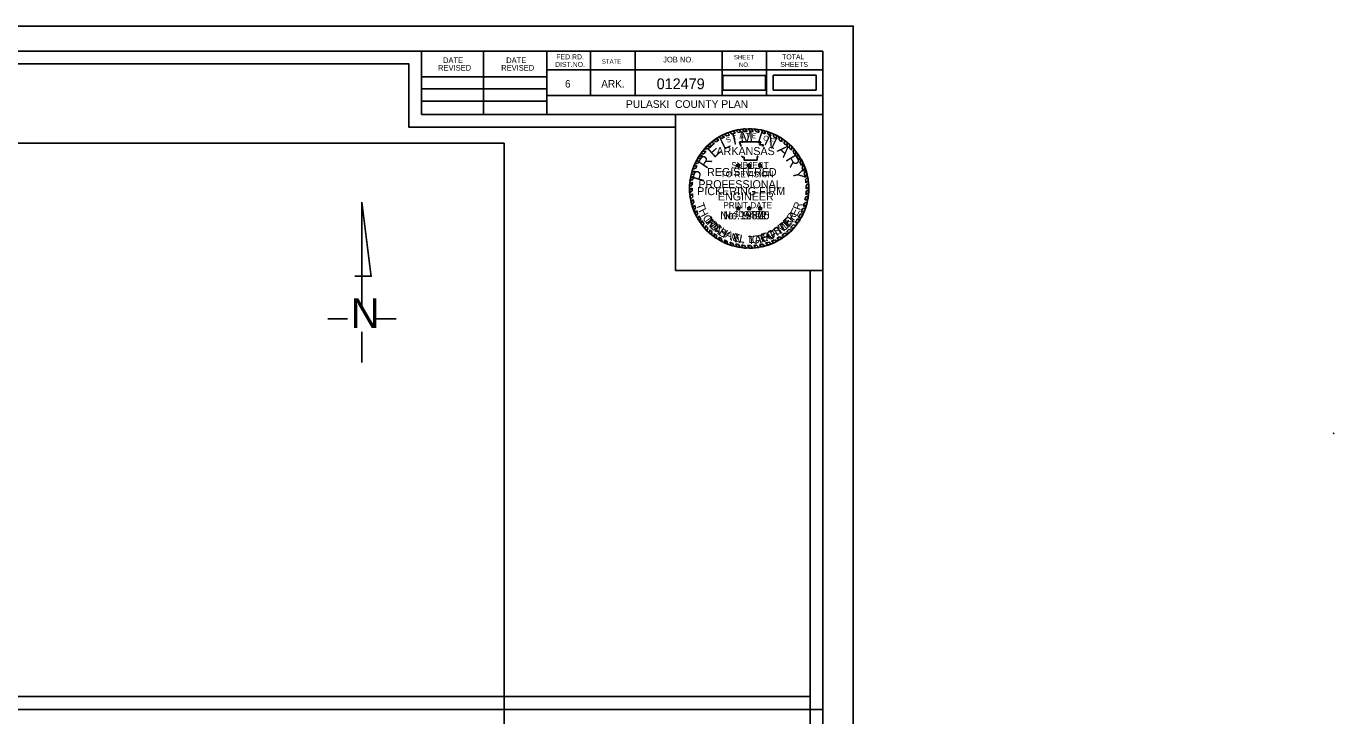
# Model space of a CAD drawing. Extents: x 10700 to 22009, y 10612 to 15552.
# Drawn here: x 19967 to 22009, y 14476 to 15552 of the extents above; entities that cross this region are included whole.
import ezdxf

# ---------------------------------------------------------------- set-up
doc = ezdxf.new("R2010")
doc.units = 0
for name, color, linetype in [('Default', 7, 'Continuous'), ('R_Border', 7, 'Continuous'), ('R_Border Notes', 7, 'Continuous'), ('R_Border Plan-Plan', 7, 'Continuous'), ('R_Draft', 7, 'Continuous'), ('R_No Plot', 7, 'Continuous'), ('STAMP_PE_CRAFTON', 7, 'Continuous'), ('STAMP_PE_FOSTER', 7, 'Continuous'), ('STAMP_PE_SEAL-INFO', 7, 'Continuous'), ('STAMP_PE_TAEGTMEYER', 7, 'Continuous'), ('STAMP_PE_TXT', 7, 'Continuous'), ('STAMP_PRELIMINARY', 7, 'Continuous')]:
    doc.layers.add(name, color=color, linetype=linetype)

msp = doc.modelspace()

# ---------------------------------------------------------------- linework, layer by layer
at = {"layer": 'Default'}
for points in [[(21054.8, 15452.2), (21121.6, 15452.2), (21121.6, 15475.3), (21054.8, 15475.3)], [(21133.5, 15452.3), (21200.3, 15452.3), (21200.3, 15475.4), (21133.5, 15475.4)], [(22008.3, 14916.3), (22008.8, 14916.3), (22008.8, 14916.8), (22008.3, 14916.8)]]:
    msp.add_lwpolyline(points, close=True, dxfattribs=at)
at = {"layer": 'R_Border'}
for p, q in [((18049.1, 15513.1), (21210.9, 15513.1)), ((20584.5, 15414.3), (20584.5, 15513.1)), ((20681.3, 15414.3), (20681.3, 15513.1)), ((20779.9, 15513.1), (20779.9, 15414.3)), ((20848.3, 15513.1), (20848.3, 15443.7)), ((20917.7, 15513.1), (20917.7, 15443.7)), ((21053.5, 15513.1), (21053.5, 15443.7)), ((21122.9, 15513.1), (21122.9, 15443.7)), ((21210.9, 13458.5), (21210.9, 15513.1)), ((21210.9, 15483.7), (20779.9, 15483.7)), ((21210.9, 15483.9), (21210.9, 15483.9)), ((20584.5, 15472.9), (20779.9, 15472.9)), ((20584.5, 15454.3), (20779.9, 15454.3)), ((21210.9, 15443.7), (20779.9, 15443.7)), ((20809.5, 15443.7), (21210.9, 15443.7)), ((20584.5, 15434.9), (20779.9, 15434.9)), ((21210.9, 15414.3), (20584.5, 15414.3))]:
    msp.add_line(p, q, dxfattribs=at)
at = {"layer": 'R_Border Plan-Plan'}
msp.add_line((18049.1, 14485.8), (21210.9, 14485.8), dxfattribs=at)
at = {"layer": 'R_Draft'}
for p, q in [((20491.3, 15277.2), (20505.9, 15160.8)), ((20491.3, 15114.5), (20491.3, 15277.2)), ((20480, 15161.7), (20505.9, 15161.7)), ((20437.8, 15095.3), (20468.7, 15095.3)), ((20511.9, 15095.3), (20544.8, 15095.3)), ((20491.3, 15027.2), (20491.3, 15075))]:
    msp.add_line(p, q, dxfattribs=at)
at = {"layer": 'R_No Plot'}
msp.add_line((17925.1, 15552.1), (21258.5, 15552.1), dxfattribs=at)
for points in [[(17925.1, 15552.1), (21258.5, 15552.1), (21258.5, 13418.7), (17925.1, 13418.7)], [(18069.1, 15493.1), (20564.5, 15493.1), (20564.5, 15394.3), (20739.9, 15394.3), (20980.9, 15394.3), (20980.9, 15171), (21190.9, 15171), (21190.9, 13478.5), (18069.1, 13478.5)], [(21190.9, 14505.8), (18069.1, 14505.8), (18069.1, 15493.1), (20564.5, 15493.1), (20564.5, 15394.3), (20739.9, 15394.3), (20980.9, 15394.3), (20980.9, 15171), (21190.9, 15171)], [(20980.9, 15414.3), (21210.9, 15414.3), (21210.9, 15171), (20980.9, 15171)], [(20713.4, 15369.5), (20713.4, 13848), (18546.7, 13848), (18546.7, 15369.5)]]:
    msp.add_lwpolyline(points, close=True, dxfattribs=at)
at = {"layer": 'STAMP_PE_SEAL-INFO'}
for p, q in [((21044.3, 15376.4), (21048.7, 15374.4)), ((21048.2, 15378.8), (21052.5, 15376.6)), ((21052.7, 15381.3), (21057.3, 15379.1)), ((21057, 15383.5), (21060.9, 15380.7)), ((21062, 15385.6), (21065, 15382.4)), ((21065.5, 15386.9), (21069.3, 15383.8)), ((21071.4, 15388.7), (21074.3, 15385.2)), ((21075.3, 15389.7), (21078.9, 15386.2)), ((21080.1, 15390.6), (21083.1, 15387)), ((21085.3, 15391.4), (21088.1, 15387.5)), ((21092.6, 15387.8), (21089.5, 15391.8)), ((21097.6, 15387.9), (21094.8, 15392)), ((21102.2, 15387.7), (21099.6, 15391.9)), ((21107.3, 15387.2), (21104.3, 15391.6)), ((21111.5, 15386.5), (21108.9, 15391.1)), ((21117.1, 15385.3), (21115.4, 15389.9)), ((21121.2, 15384.2), (21119.6, 15388.9)), ((21125.7, 15382.8), (21124.3, 15387.6)), ((21129.9, 15381.2), (21128.4, 15386.1)), ((21134.5, 15379.1), (21133.4, 15384.1)), ((21138.9, 15376.8), (21138.1, 15381.9)), ((21142.8, 15374.6), (21142.4, 15379.6)), ((21147.1, 15371.7), (21146.8, 15376.9)), ((21022.9, 15356.7), (21028.3, 15356.9)), ((21026.3, 15360.8), (21031.5, 15360.4)), ((21029.5, 15364.2), (21035, 15363.8)), ((21032.9, 15367.5), (21037.5, 15366.1)), ((21036.3, 15370.5), (21041.6, 15369.4)), ((21040.1, 15373.7), (21044.7, 15371.7)), ((21080.7, 15371.7), (21114.1, 15371.7)), ((21081.9, 15368.6), (21080.7, 15371.7)), ((21082.9, 15365.6), (21081.9, 15368.6)), ((21083, 15364.5), (21082.9, 15365.6)), ((21114.1, 15371.7), (21111.8, 15366.8)), ((21111.8, 15366.8), (21118.2, 15366.8)), ((21118.2, 15366.8), (21116.7, 15364.5)), ((21150.8, 15369), (21151.1, 15373.9)), ((21155.2, 15365.3), (21155.4, 15370.5)), ((21158.3, 15362.4), (21159, 15367.4)), ((21161.9, 15358.7), (21162.6, 15363.9)), ((21164.7, 15355.5), (21166, 15360.2)), ((21167.9, 15351.3), (21169.3, 15356.3)), ((21011.1, 15337.4), (21016.1, 15338.4)), ((21013, 15341.3), (21017.9, 15341.9)), ((21015.3, 15345.5), (21020.2, 15345.7)), ((21017.7, 15349.5), (21022.9, 15349.9)), ((21020.1, 15353), (21025.1, 15352.9)), ((21084.9, 15347.4), (21084.6, 15349.6)), ((21088, 15347.4), (21084.9, 15347.4)), ((21088, 15343.1), (21088, 15347.4)), ((21108.3, 15343.1), (21088, 15343.1)), ((21108.5, 15346.5), (21108.3, 15343.1)), ((21109.3, 15349.6), (21108.5, 15346.5)), ((21170.1, 15348.2), (21171.9, 15352.8)), ((21173.2, 15343.2), (21175, 15348.1)), ((21175.2, 15339.5), (21177.5, 15344)), ((21177.5, 15334.7), (21179.8, 15339.5)), ((21178.9, 15331.3), (21181.5, 15335.7)), ((21008.8, 15317.4), (21004.1, 15314.9)), ((21005.1, 15319.9), (21009.8, 15321.8)), ((21006.2, 15324), (21010.9, 15325.7)), ((21007.7, 15329), (21012.6, 15330.4)), ((21009.2, 15333.1), (21014.3, 15334.5)), ((21180.9, 15325.8), (21183.6, 15330.6)), ((21181.9, 15322.2), (21184.9, 15326.7)), ((21183.3, 15316.6), (21186.4, 15321.1)), ((21183.9, 15312.8), (21187.5, 15316.3)), ((21007, 15304.2), (21002.7, 15301.7)), ((21006.8, 15299.3), (21002.7, 15296)), ((21006.9, 15295.2), (21002.9, 15292)), ((21007.3, 15308.5), (21003, 15305.7)), ((21007.9, 15312.8), (21003.5, 15310.6)), ((21184.6, 15307.7), (21188.3, 15311.1)), ((21184.9, 15303.5), (21188.8, 15306.4)), ((21184.9, 15294.3), (21189.1, 15297.1)), ((21185.1, 15298.3), (21189.1, 15301.6)), ((21007.2, 15290.3), (21003.5, 15286.7)), ((21007.7, 15286), (21004.2, 15282.3)), ((21008.5, 15281.4), (21005.1, 15277.7)), ((21009.4, 15277.2), (21006.3, 15273.1)), ((21182.1, 15275.8), (21186.8, 15277.8)), ((21183.1, 15280.3), (21187.7, 15282.3)), ((21184, 15285.3), (21188.5, 15287.5)), ((21184.6, 15289.2), (21188.9, 15291.8)), ((21010.7, 15272.7), (21007.7, 15268.6)), ((21012.1, 15268.5), (21009.3, 15264.4)), ((21013.7, 15264.3), (21011.1, 15260)), ((21015.5, 15260.4), (21013.2, 15255.8)), ((21017.8, 15255.8), (21015.9, 15250.9)), ((21172.8, 15253.6), (21177.8, 15254.1)), ((21175.5, 15258.6), (21180.4, 15259.3)), ((21177.1, 15261.9), (21182, 15262.9)), ((21179.2, 15267.1), (21184.1, 15268.4)), ((21180.6, 15270.9), (21185.5, 15272.9)), ((21020.2, 15251.8), (21018.3, 15247.1)), ((21022.2, 15248.7), (21021.1, 15243.2)), ((21025, 15244.8), (21024, 15239.5)), ((21028, 15241), (21027.2, 15235.8)), ((21031.1, 15237.6), (21030.4, 15232.4)), ((21034.3, 15234.4), (21034, 15229.1)), ((21158.2, 15235), (21162.6, 15233.6)), ((21160.7, 15237.6), (21165.5, 15236.7)), ((21164.6, 15241.9), (21169.2, 15241.1)), ((21167.7, 15245.8), (21172.7, 15245.9)), ((21171.1, 15250.8), (21175.8, 15250.7)), ((21037.7, 15231.2), (21037.7, 15226)), ((21041.3, 15228.3), (21041.5, 15223.1)), ((21044.7, 15225.8), (21045.1, 15220.6)), ((21049, 15223), (21049.6, 15217.9)), ((21052.5, 15220.9), (21053.4, 15215.8)), ((21057.3, 15218.4), (21058.9, 15213.2)), ((21061, 15216.7), (21062.8, 15211.6)), ((21066, 15214.8), (21068, 15209.8)), ((21070, 15213.5), (21072.3, 15208.6)), ((21121.5, 15213.4), (21125.6, 15210.4)), ((21126.4, 15215), (21130.8, 15212.3)), ((21130.6, 15216.6), (21134.8, 15214)), ((21135.2, 15218.7), (21140, 15216.6)), ((21139.2, 15220.9), (21143.4, 15218.5)), ((21143.4, 15223.3), (21147.9, 15221.4)), ((21146.8, 15225.6), (21151.2, 15223.7)), ((21151.4, 15229), (21156.1, 15227.6)), ((21154.1, 15231.3), (21158.9, 15230)), ((21075.1, 15212.1), (21077.2, 15207.4)), ((21079.1, 15211.2), (21081.6, 15206.6)), ((21084.1, 15210.4), (21086.5, 15206)), ((21088.5, 15209.9), (21091.2, 15205.7)), ((21093.3, 15209.7), (21096.3, 15205.5)), ((21097.9, 15209.6), (21101.4, 15205.7)), ((21103.1, 15209.9), (21106.4, 15206.1)), ((21107.5, 15210.4), (21111.2, 15206.8)), ((21111.9, 15211.1), (21115.8, 15207.7)), ((21116.9, 15212.1), (21120.6, 15208.9))]:
    msp.add_line(p, q, dxfattribs=at)
for radius, start, end in [(93.2, 123.6199, 126.5906), (93.2, 117.6544, 120.8099), (89.1, 115.6869, 119.1583), (93.2, 111.3124, 114.7026), (89.1, 110.3086, 113.1659), (93.2, 105.2339, 109.0352), (89.1, 104.0352, 107.3615), (93.2, 99.7525, 102.7765), (89.1, 98.258, 101.0329), (93.2, 93.9381, 96.5517), (89.1, 92.1102, 95.0367), (93.2, 87.7298, 90.6707), (89.1, 85.9628, 88.9097), (93.2, 81.9732, 84.8236), (89.1, 79.9264, 82.696), (93.2, 75.3125, 77.9426), (89.1, 73.5575, 76.2314), (93.2, 69.6061, 72.3058), (89.1, 67.6248, 70.504), (93.2, 63.1329, 66.2704), (89.1, 61.1558, 64.3784), (93.2, 56.9003, 60.0942), (93.2, 141.6056, 144.4486), (89.1, 139.301, 142.5873), (93.2, 135.4021, 138.3031), (89.1, 133.1331, 136.2562), (93.2, 129.7326, 132.5376), (89.1, 127.5297, 130.9683), (89.1, 121.9746, 125.11), (89.1, 54.9238, 58.2702), (89.1, 48.3016, 52.0395), (93.2, 50.3492, 53.7159), (89.1, 42.2212, 45.5512), (93.2, 44.3405, 47.3929), (89.1, 36.135, 39.5311), (93.2, 38.1247, 41.2316), (93.2, 152.864, 155.5189), (93.2, 147.0072, 149.899), (89.1, 151.0315, 153.573), (89.1, 145.0197, 148.2104), (89.1, 29.9032, 33.6645), (93.2, 31.9614, 35.4294), (89.1, 23.7732, 27.2211), (93.2, 25.9391, 29.0125), (93.2, 19.9538, 23.3141), (93.2, 170.0003, 172.6878), (93.2, 164.3068, 166.894), (93.2, 158.4077, 161.0701), (89.1, 167.9048, 170.9039), (89.1, 162.4331, 165.0013), (89.1, 156.3402, 159.2319), (89.1, 17.6802, 21.4251), (89.1, 11.5444, 15.2364), (93.2, 13.8421, 17.4447), (93.2, 7.5852, 10.8621), (93.2, 175.7409, 178.2066), (93.2, 181.7251, 184.1626), (89.1, 179.6454, 182.2633), (89.1, 173.73, 176.4734), (89.1, 5.7599, 9.0606), (89.1, 353.8632, 357.1274), (89.1, 359.7329, 3.0639), (93.2, 1.7215, 4.7268), (93.2, 355.7156, 358.9569), (93.2, 187.4204, 190.1927), (93.2, 193.0369, 195.9973), (89.1, 185.4539, 188.234), (89.1, 191.2274, 193.9858), (89.1, 341.777, 345.0925), (89.1, 348.0778, 351.3435), (93.2, 343.8925, 347.035), (93.2, 349.8305, 353.0885), (93.2, 198.8967, 201.6281), (89.1, 196.9675, 199.8353), (93.2, 204.5479, 207.4328), (89.1, 202.7761, 205.4791), (89.1, 208.7883, 211.7934), (89.1, 329.5549, 333.2076), (89.1, 335.6038, 339.1858), (93.2, 331.4037, 334.9332), (93.2, 337.3837, 340.9933), (93.2, 210.8636, 213.6571), (93.2, 216.6115, 219.491), (89.1, 214.1838, 217.2747), (93.2, 222.48, 225.3801), (89.1, 220.3909, 223.3056), (89.1, 226.2494, 229.2407), (89.1, 310.7744, 314.3161), (93.2, 312.4518, 315.6633), (89.1, 316.6531, 320.3711), (93.2, 318.2846, 321.8043), (89.1, 323.5851, 327.4407), (93.2, 325.4405, 328.9872), (93.2, 228.3665, 231.348), (89.1, 232.229, 234.9336), (93.2, 234.295, 236.9452), (89.1, 238.2223, 240.8353), (93.2, 240.1977, 242.8613), (89.1, 244.3204, 246.9486), (93.2, 246.576, 249.1558), (89.1, 250.3491, 253.1216), (89.1, 286.6423, 289.9783), (93.2, 288.5709, 291.9733), (89.1, 292.8745, 296.1185), (93.2, 294.6481, 298.2166), (89.1, 299.0768, 302.1724), (93.2, 300.621, 303.8703), (89.1, 304.823, 308.5143), (93.2, 306.3721, 310.208), (93.2, 252.5967, 255.3252), (89.1, 256.505, 259.1192), (93.2, 258.4433, 261.1398), (89.1, 262.3783, 265.2012), (93.2, 264.1978, 267.1009), (89.1, 268.3215, 271.277), (93.2, 270.2548, 273.3361), (89.1, 274.6157, 277.4486), (93.2, 276.4239, 279.4357), (89.1, 280.3459, 283.5814), (93.2, 282.3199, 285.3702)]:
    msp.add_arc((21095.9, 15298.8), radius, start, end, dxfattribs=at)
at = {"layer": 'STAMP_PE_TXT'}
for p, q in [((21077.7, 15334.5), (21075.7, 15335.9)), ((21075.7, 15335.9), (21078.2, 15335.9)), ((21078.2, 15335.9), (21078.9, 15338.2)), ((21078.9, 15338.2), (21079.7, 15335.9)), ((21079.7, 15335.9), (21082.2, 15335.9)), ((21082.2, 15335.9), (21080.2, 15334.5)), ((21094.7, 15334.5), (21092.7, 15335.9)), ((21092.7, 15335.9), (21095.2, 15335.9)), ((21095.2, 15335.9), (21095.9, 15338.2)), ((21095.9, 15338.2), (21096.7, 15335.9)), ((21096.7, 15335.9), (21099.1, 15335.9)), ((21099.1, 15335.9), (21097.2, 15334.5)), ((21111.7, 15334.5), (21109.7, 15335.9)), ((21109.7, 15335.9), (21112.1, 15335.9)), ((21112.1, 15335.9), (21112.9, 15338.2)), ((21112.9, 15338.2), (21113.7, 15335.9)), ((21113.7, 15335.9), (21116.1, 15335.9)), ((21116.1, 15335.9), (21114.1, 15334.5)), ((21077, 15332.1), (21077.7, 15334.5)), ((21078.9, 15333.6), (21077, 15332.1)), ((21080.9, 15332.1), (21078.9, 15333.6)), ((21080.2, 15334.5), (21080.9, 15332.1)), ((21093.9, 15332.1), (21094.7, 15334.5)), ((21095.9, 15333.6), (21093.9, 15332.1)), ((21097.9, 15332.1), (21095.9, 15333.6)), ((21097.2, 15334.5), (21097.9, 15332.1)), ((21110.9, 15332.1), (21111.7, 15334.5)), ((21112.9, 15333.6), (21110.9, 15332.1)), ((21114.9, 15332.1), (21112.9, 15333.6)), ((21114.1, 15334.5), (21114.9, 15332.1)), ((21077.7, 15267.4), (21075.7, 15268.8)), ((21075.7, 15268.8), (21078.2, 15268.8)), ((21077, 15265.1), (21077.7, 15267.4)), ((21078.9, 15266.5), (21077, 15265.1)), ((21078.2, 15268.8), (21078.9, 15271.2)), ((21078.9, 15271.2), (21079.7, 15268.8)), ((21080.9, 15265.1), (21078.9, 15266.5)), ((21079.7, 15268.8), (21082.2, 15268.8)), ((21082.2, 15268.8), (21080.2, 15267.4)), ((21080.2, 15267.4), (21080.9, 15265.1)), ((21094.7, 15267.4), (21092.7, 15268.8)), ((21092.7, 15268.8), (21095.2, 15268.8)), ((21093.9, 15265.1), (21094.7, 15267.4)), ((21095.9, 15266.5), (21093.9, 15265.1)), ((21095.2, 15268.8), (21095.9, 15271.2)), ((21095.9, 15271.2), (21096.7, 15268.8)), ((21097.9, 15265.1), (21095.9, 15266.5)), ((21096.7, 15268.8), (21099.1, 15268.8)), ((21099.1, 15268.8), (21097.2, 15267.4)), ((21097.2, 15267.4), (21097.9, 15265.1)), ((21111.7, 15267.4), (21109.7, 15268.8)), ((21109.7, 15268.8), (21112.1, 15268.8)), ((21110.9, 15265.1), (21111.7, 15267.4)), ((21112.9, 15266.5), (21110.9, 15265.1)), ((21112.1, 15268.8), (21112.9, 15271.2)), ((21112.9, 15271.2), (21113.7, 15268.8)), ((21114.9, 15265.1), (21112.9, 15266.5)), ((21113.7, 15268.8), (21116.1, 15268.8)), ((21116.1, 15268.8), (21114.1, 15267.4)), ((21114.1, 15267.4), (21114.9, 15265.1))]:
    msp.add_line(p, q, dxfattribs=at)
at = {"layer": 'STAMP_PRELIMINARY'}
msp.add_circle((21095.9, 15298.8), 93.2, dxfattribs=at)

# ---------------------------------------------------------------- texts
at = {"layer": 'R_Border'}
for s, height, p in [('DATE', 8.79, (20617.9, 15494.5)), ('DATE', 8.79, (20716.5, 15494.5)), ('FED.RD.', 7.82, (20794.7, 15500.3)), ('STATE', 6.84, (20865.9, 15493.5)), ('JOB NO.', 8.79, (20961.7, 15495.5)), ('SHEET', 6.84, (21072.1, 15500.3)), ('TOTAL', 7.82, (21147.3, 15500.3)), ('REVISED', 8.79, (20610.1, 15482.7)), ('REVISED', 8.79, (20708.7, 15482.7)), ('DIST.NO.', 7.82, (20792.7, 15488.5)), ('NO.', 6.84, (21079.9, 15488.5)), ('SHEETS', 7.82, (21144.5, 15488.5)), ('6', 11.7, (20808.3, 15456.3)), ('ARK.', 11.72, (20864.9, 15456.3))]:
    msp.add_text(s, height=height, rotation=360, dxfattribs=at).set_placement(p)
at = {"layer": 'R_Border Notes'}
for s, height, p in [('012479', 16.8, (20951.5, 15453.8)), ('PULASKI  COUNTY PLAN', 12, (20903.5, 15424.5))]:
    msp.add_text(s, height=height, dxfattribs=at).set_placement(p)
at = {"layer": 'R_Draft'}
msp.add_text('N', height=46.5, dxfattribs=at).set_placement((20473.7, 15081))
at = {"layer": 'STAMP_PE_CRAFTON'}
for s, rotation, p in [('T', 310.7442, (21025.6, 15247.7)), ('No. 12370', 360, (21050.5, 15250.7)), ('N', 49.2411, (21158.7, 15239)), ('O', 317.6422, (21032.3, 15239.6)), ('N', 324.4537, (21040.7, 15231.8)), ('Y', 331.1686, (21051, 15224.6)), ('F', 28.7821, (21132.5, 15220.1)), ('T', 34.1136, (21141.7, 15225.1)), ('O', 41.8391, (21150.3, 15231.2)), ('N', 347.4752, (21071.6, 15215.5)), ('.', 356.8926, (21083.9, 15212.7)), ('C', 6.0117, (21100.6, 15212.2)), ('R', 14.8189, (21111.6, 15213.3)), ('A', 20.5125, (21122.7, 15216.3))]:
    msp.add_text(s, height=12.5, rotation=rotation, dxfattribs=at).set_placement(p)
at = {"layer": 'STAMP_PE_FOSTER'}
for s, height, rotation, p in [('M', 12, 308.339, (21027.1, 15249)), ('No. 9402', 12.5, 360, (21055.8, 15250.7)), ('E', 12, 46.9613, (21155.9, 15238.7)), ('R', 12, 54.5031, (21163.2, 15246.9)), ('I', 12, 314.1842, (21035.1, 15239.6)), ('C', 12, 319.8733, (21038.6, 15236.1)), ('H', 12, 327.7235, (21047.9, 15228.7)), ('O', 12, 23.719, (21126.7, 15219.6)), ('S', 12, 31.7234, (21137.8, 15224.9)), ('T', 12, 39.4194, (21147.3, 15231.2)), ('A', 12, 335.7276, (21057.7, 15222.9)), ('E', 12, 343.5779, (21069.1, 15218.2)), ('L', 12, 350.8115, (21079.7, 15215.4)), ('L', 12, 1.2666, (21095.1, 15213.8)), ('.', 12, 6.8035, (21105.5, 15214.4)), ('F', 12, 15.8691, (21116.3, 15216.3))]:
    msp.add_text(s, height=height, rotation=rotation, dxfattribs=at).set_placement(p)
at = {"layer": 'STAMP_PE_TAEGTMEYER'}
for s, rotation, p in [('T', 289.646, (21012.9, 15273.9)), ('R', 69.57, (21175.4, 15263.9)), ('H', 296.7339, (21016.5, 15264)), ('O', 303.7708, (21022.4, 15252.9)), ('No. 19605', 360, (21050.5, 15250.7)), ('Y', 53.9986, (21163.7, 15244.7)), ('E', 63.0984, (21170.4, 15254.1)), ('M', 314.2033, (21028.9, 15243.4)), ('A', 321.0594, (21038.6, 15233.8)), ('S', 327.8239, (21046.8, 15227.3)), ('T', 31.466, (21136.9, 15222.3)), ('M', 39.3, (21145.9, 15227.7)), ('E', 46.8094, (21156.3, 15236.5)), ('N', 344.2727, (21065.8, 15217.3)), ('.', 350.6464, (21077.9, 15214)), ('T', 3.0061, (21094.6, 15212)), ('A', 8.9826, (21105, 15212.5)), ('E', 17.6836, (21115.4, 15214.1)), ('G', 23.3052, (21125.9, 15217.4))]:
    msp.add_text(s, height=12.5, rotation=rotation, dxfattribs=at).set_placement(p)
at = {"layer": 'STAMP_PE_TXT'}
for s, height, rotation, p in [('S', 7.81, 23.5541, (21061.9, 15369.8)), ('T', 7.81, 16.311, (21071.1, 15373.5)), ('A', 7.81, 9.0679, (21080.8, 15376)), ('T', 7.81, 1.8248, (21090.6, 15377.3)), ('E', 7.81, 355.2002, (21099.7, 15377.4)), ('O', 7.81, 342.2506, (21117, 15374.7)), ('F', 7.81, 335.0075, (21126.7, 15371.3)), ('ARKANSAS', 12.5, 360, (21044.8, 15350.9)), ('REGISTERED', 12.5, 360, (21030.1, 15318.2)), ('PROFESSIONAL', 12.5, 360, (21016.6, 15299.2)), ('ENGINEER', 12.5, 360, (21047, 15280.1))]:
    msp.add_text(s, height=height, rotation=rotation, dxfattribs=at).set_placement(p)
at = {"layer": 'STAMP_PRELIMINARY'}
for s, height, rotation, p in [('L', 18, 25.513, (21056, 15359)), ('I', 18, 12.5248, (21071.3, 15366.6)), ('M', 18, 3.1074, (21082.3, 15369.7)), ('I', 18, 342.3164, (21107, 15370.4)), ('N', 18, 333.9382, (21118, 15367.6)), ('E', 18, 42.3578, (21041.2, 15345.7)), ('A', 18, 315.6579, (21138.4, 15357.4)), ('R', 18, 56.2292, (21029.6, 15328.4)), ('SUBJECT', 9.6, 360, (21067.9, 15330.3)), ('R', 18, 301.3831, (21152.1, 15344.3)), ('P', 18, 73.913, (21024.1, 15308.2)), ('TO REVISION', 9.6, 360, (21051.3, 15316.4)), ('Y', 18, 283.2593, (21162.9, 15326.4)), ('PICKERING FIRM', 12.5, 360, (21014.7, 15288.4)), ('PRINT DATE', 9.6, 360, (21055.5, 15267.9)), ('$DATE$', 9.6, 360, (21072.3, 15254.1))]:
    msp.add_text(s, height=height, rotation=rotation, dxfattribs=at).set_placement(p)

doc.saveas('drawing.dxf')
